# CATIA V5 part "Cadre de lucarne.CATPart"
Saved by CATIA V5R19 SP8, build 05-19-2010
Part number: Cadre de lucarne
Revision: ANY
Definition: UNKNOWN
Nomenclature: Cadre de lucarne
Source: Unknown
Bounding box of the stored display mesh (mm): x -300 to 300, y -300 to 300, z 0 to 5
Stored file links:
  D:\Documents\1_Travail\1 - ac-limoges.fr\OneDrive - ac-limoges.fr\STI2D_Turgot\2 -2I2D\3_SEQUENCE_Serre_Connectée\3- Spécificités\ITEC\EC 3 Ouverture automatique\Simulation  Ouverture Automatique\Cadre de lucarne.CATPart
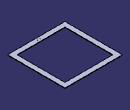
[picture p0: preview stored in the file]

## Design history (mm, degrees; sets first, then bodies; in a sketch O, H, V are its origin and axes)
AxisSystem1: origin (0, 0, 0), X (1, 0, 0), Y (0, 0.866, 0.5), Z (0, -0.5, 0.866)
Body1 "NONE" (main body)
  Solid1: solid without history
